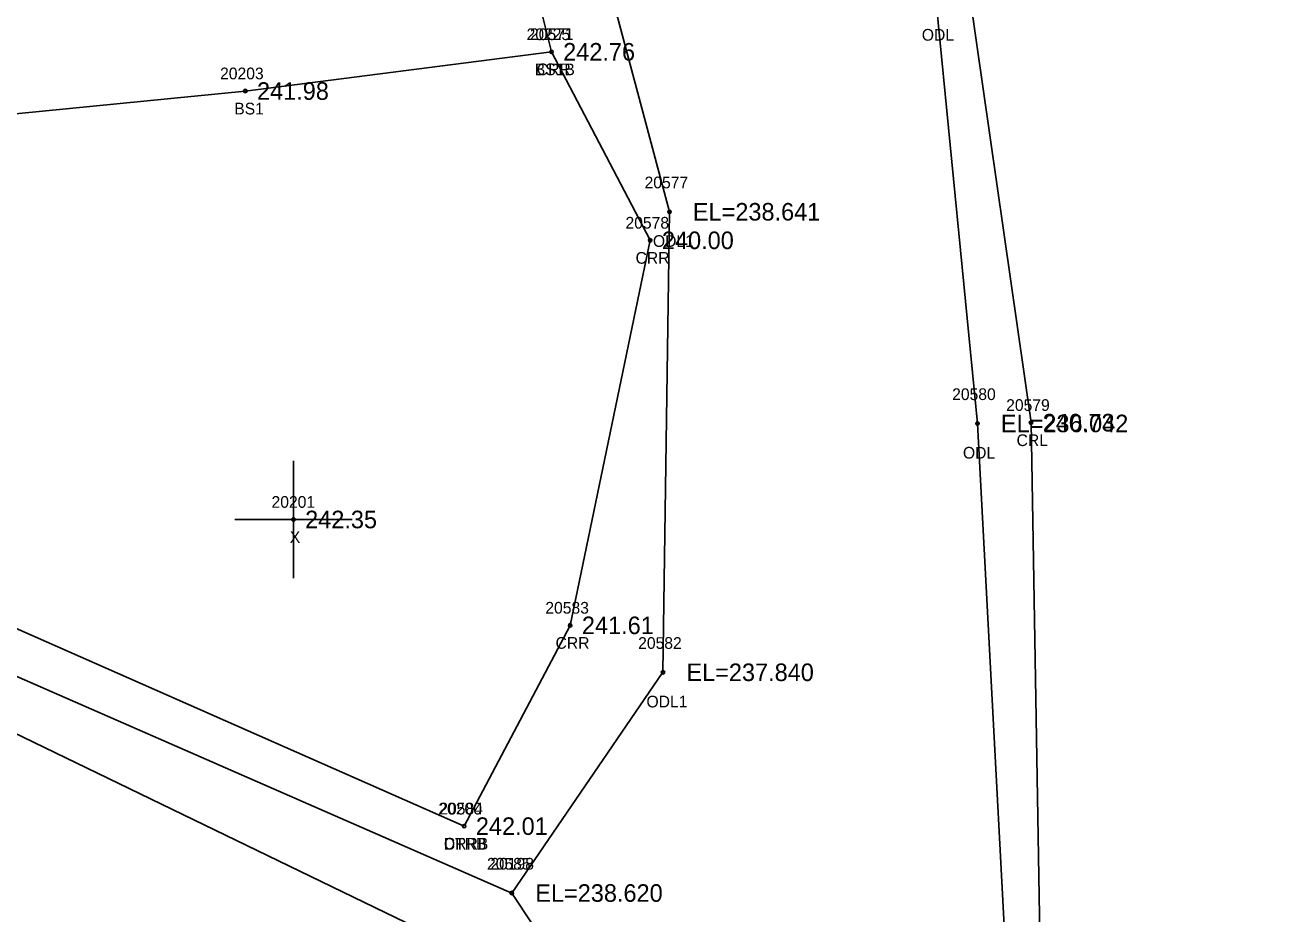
# Model space of a CAD drawing. Extents: x 2275563 to 2277161, y 1075719 to 1076412.
# Drawn here: x 2276292.5 to 2276399.9, y 1075959.9 to 1076035.8 of the extents above; entities that cross this region are included whole.
import ezdxf

# ---------------------------------------------------------------- set-up
doc = ezdxf.new("R2010")
doc.units = 0
for name, color, linetype in [('RD_DTM_BkLn2', 7, 'Continuous'), ('RD_DTM_BkLn_txCode', 7, 'Continuous'), ('RD_EX_H2O', 7, 'Continuous'), ('RD_EX_H2O_txCode', 7, 'Continuous'), ('RD_EX_Misc', 7, 'Continuous'), ('RD_EX_Misc_txCode', 7, 'Continuous'), ('RD_EX_TX_H2O_ELEV', 7, 'Continuous'), ('RD_EX_TX_Misc_ELEV', 7, 'Continuous'), ('RD_SMD_Locator', 7, 'Continuous')]:
    doc.layers.add(name, color=color, linetype=linetype)

msp = doc.modelspace()

# ---------------------------------------------------------------- linework, layer by layer
at = {"layer": 'RD_DTM_BkLn2'}
msp.add_lwpolyline([(2276200.36, 1076021.35), (2276242.06, 1076023.32), (2276311.29, 1076030.17), (2276337.42, 1076033.52)], dxfattribs=at)
at = {"layer": 'RD_EX_H2O'}
for points in [[(2276371.99, 1076084.86), (2276373.47, 1076057.63), (2276371.02, 1076053.34), (2276370.27, 1076037.47), (2276373.78, 1076001.78), (2276377.12, 1075939.07), (2276387.12, 1075924.65), (2276409.24, 1075914.33), (2276440.66, 1075900.23), (2276458.72, 1075909.41), (2276468.75, 1075909.62), (2276481.14, 1075898.88), (2276470.97, 1075847.84), (2276468.69, 1075801.1), (2276495.71, 1075755.91), (2276526.48, 1075747.54)], [(2276337.52, 1076082.32), (2276336.19, 1076056.07), (2276339.64, 1076049.32), (2276347.49, 1076019.86), (2276346.94, 1075980.53), (2276334.04, 1075961.68), (2276358.91, 1075924.16), (2276390.72, 1075889.91), (2276404.64, 1075906.32), (2276409.35, 1075902.87), (2276425.82, 1075890.52), (2276463.29, 1075896.33), (2276470.94, 1075887.1), (2276454.43, 1075853.34), (2276454.95, 1075812.59), (2276477.48, 1075753.76), (2276516.05, 1075739.78)], [(2276374.66, 1076053.77), (2276373.09, 1076038.49), (2276378.35, 1076001.85), (2276379.41, 1075939.56), (2276393.18, 1075928.69), (2276410.52, 1075916.05), (2276439.66, 1075905.97), (2276458.4, 1075912.38), (2276470.74, 1075911.86), (2276484.27, 1075900.43), (2276472.97, 1075846.67), (2276473.8, 1075804.25), (2276499.15, 1075757.95), (2276529.69, 1075749.92)], [(2276334.2, 1076046.4), (2276337.42, 1076033.52), (2276345.85, 1076017.42), (2276339.02, 1075984.54), (2276329.97, 1075967.39)], [(2275584.42, 1075945.55), (2275630.75, 1075959.99), (2275679.72, 1075972.8), (2275727.1, 1075983.01), (2275776.52, 1075992.46), (2275822.09, 1075998.61), (2275868.31, 1076005.5), (2275971.07, 1076013.85), (2276058.03, 1076018.84), (2276110, 1076025.4), (2276114.25, 1076022.31), (2276152.59, 1076021.64), (2276188.46, 1076022.22), (2276200.36, 1076021.35), (2276207.63, 1076015.4), (2276245.53, 1076014.24), (2276263.41, 1076017.81), (2276276.57, 1076007.97), (2276280.95, 1075989.03), (2276329.97, 1075967.39)], [(2275584.66, 1075942.4), (2275631.99, 1075956.6), (2275680.23, 1075970.55), (2275727.34, 1075980.71), (2275776.9, 1075989.93), (2275822.49, 1075996.83), (2275868.2, 1076003.14), (2275971.77, 1076011.3), (2276058.74, 1076015.62), (2276117.31, 1076020.2), (2276152.71, 1076018.31), (2276188.2, 1076020.3), (2276200.59, 1076018.25), (2276207.46, 1076011.88), (2276246.17, 1076010.02), (2276264.15, 1076012.48), (2276274.37, 1076006.56), (2276276.43, 1075986.9), (2276334.04, 1075961.68)], [(2275587.87, 1075932.23), (2275632.3, 1075945.74), (2275680.34, 1075962.3), (2275730.43, 1075971.98), (2275777.84, 1075981.49), (2275823.91, 1075987.34), (2275869.26, 1075992.75), (2275941.88, 1076000), (2275968.29, 1076005.71), (2275973.41, 1076009.09), (2276058.49, 1076013.63), (2276114.54, 1076018.47), (2276125.61, 1076012.99), (2276153.29, 1076014.06), (2276186.69, 1076017.67), (2276196.76, 1076016.05), (2276210.13, 1076008.45), (2276246.2, 1076005.42), (2276264.34, 1076010.6), (2276271.38, 1076006), (2276275.05, 1075983.37), (2276331.39, 1075956.06)]]:
    msp.add_lwpolyline(points, dxfattribs=at)
at = {"layer": 'RD_EX_Misc'}
for p, q in [((2276315.4, 1075988.58), (2276315.4, 1075998.58)), ((2276310.4, 1075993.58), (2276320.4, 1075993.58))]:
    msp.add_line(p, q, dxfattribs=at)
at = {"layer": 'RD_SMD_Locator'}
for centre in [(2276337.42, 1076033.52), (2276337.42, 1076033.52), (2276311.29, 1076030.17), (2276347.49, 1076019.86), (2276345.85, 1076017.42), (2276378.35, 1076001.85), (2276373.78, 1076001.78), (2276315.4, 1075993.58), (2276339.02, 1075984.54), (2276346.94, 1075980.53), (2276329.97, 1075967.39), (2276329.97, 1075967.39), (2276334.04, 1075961.68), (2276334.04, 1075961.68)]:
    msp.add_circle(centre, 0.15, dxfattribs=at)

# ---------------------------------------------------------------- texts
at = {"layer": 'RD_DTM_BkLn_txCode'}
for s, p in [('20225', (2276335.3, 1076034.52)), ('20203', (2276309.14, 1076031.17)), ('BS1B', (2276336, 1076031.52)), ('BS1', (2276310.35, 1076028.17))]:
    msp.add_text(s, height=1, dxfattribs=at).set_placement(p)
at = {"layer": 'RD_EX_H2O_txCode'}
for s, p in [('20571', (2276335.59, 1076034.52)), ('ODL', (2276369.03, 1076034.47)), ('CRR', (2276336.17, 1076031.52)), ('20577', (2276345.37, 1076021.86)), ('20578', (2276343.74, 1076018.42)), ('ODL1', (2276346.08, 1076016.86)), ('CRR', (2276344.6, 1076015.42)), ('20580', (2276371.62, 1076003.78)), ('20579', (2276376.23, 1076002.85)), ('CRL', (2276377.12, 1075999.85)), ('ODL', (2276372.54, 1075998.78)), ('20583', (2276336.9, 1075985.54)), ('CRR', (2276337.77, 1075982.54)), ('20582', (2276344.82, 1075982.53)), ('ODL1', (2276345.53, 1075977.53)), ('20200', (2276327.77, 1075968.39)), ('20584', (2276327.85, 1075968.39)), ('CRRB', (2276328.24, 1075965.39)), ('DTRB', (2276328.23, 1075965.39)), ('20585', (2276331.92, 1075963.68)), ('20198', (2276332.21, 1075963.68))]:
    msp.add_text(s, height=1, dxfattribs=at).set_placement(p)
at = {"layer": 'RD_EX_Misc_txCode'}
for s, p in [('20201', (2276313.53, 1075994.58)), ('X', (2276315.09, 1075991.58))]:
    msp.add_text(s, height=1, dxfattribs=at).set_placement(p)
at = {"layer": 'RD_EX_TX_H2O_ELEV'}
for s, p in [('242.76', (2276338.42, 1076032.77)), ('EL=238.641', (2276349.49, 1076019.11)), ('240.00', (2276346.85, 1076016.67)), ('EL=236.042', (2276375.78, 1076001.03)), ('240.73', (2276379.35, 1076001.1)), ('241.61', (2276340.02, 1075983.79)), ('EL=237.840', (2276348.94, 1075979.78)), ('242.01', (2276330.97, 1075966.64)), ('242.01', (2276330.97, 1075966.64)), ('EL=238.620', (2276336.04, 1075960.93)), ('EL=238.620', (2276336.04, 1075960.93))]:
    msp.add_text(s, height=1.5, dxfattribs=at).set_placement(p)
at = {"layer": 'RD_EX_TX_Misc_ELEV'}
for s, p in [('242.76', (2276338.42, 1076032.77)), ('241.98', (2276312.29, 1076029.42)), ('242.35', (2276316.4, 1075992.83))]:
    msp.add_text(s, height=1.5, dxfattribs=at).set_placement(p)

doc.saveas('drawing.dxf')
